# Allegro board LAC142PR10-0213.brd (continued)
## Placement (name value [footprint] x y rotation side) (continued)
R156  0_0603_5%  [R_0603]  33.04 74.76 90 top
R157  0_0603_5%  [R_0603]  43.57 64.96 270 top
R158  1K_0402_5%  [R_0402]  82.92 82.22 90 top
R159  1K_0402_5%  [R_0402]  94.47 86.68 0 bottom
R160  0_0603_5%  [R_0603]  162.36 18.35 270 bottom
R346  22K_0402_5%  [R_0402]  118.29 111.43 90 top
R347  22K_0402_5%  [R_0402]  144.51 95.38 0 top
R348  22K_0402_5%  [R_0402]  144.51 94.49 0 top
R365  100K_0402_5%  [R_0402]  63.3 169.88 270 top
R366  100K_0402_5%  [R_0402]  102.67 110.25 270 top
R384  10K_0402_5%  [R_0402]  63.3 173.43 270 top
R400  2K_0402_1%  [R_0402]  97.14 91.82 0 top
R401  150_0402_1%  [R_0402]  99.83 91.82 180 top
R404  1.69K_0402_1%  [R_0402]  116.72 90.42 180 top
R407  0_0402_5%  [R0402_0OHM]  63.3 171.65 270 top
R437  1K_0402_5%  [R_0402]  147.68 131.7 0 top
R438  47K_0402_5%  [R_0402]  147.68 134.37 0 top
R449  33_0402_5%  [R_0402]  148.18 88.32 0 top
R450  0_0402_5%  [R0402_0OHM]  142.06 84.2 180 bottom
R452  10K_0402_5%  [R_0402]  163.23 19.32 180 bottom
R541  196_0402_1%  [R_0402]  114.66 93.85 0 top
R542  196_0402_1%  [R_0402]  116.72 91.31 180 top
R602  33_0402_5%  [R_0402]  140.21 86.04 180 bottom
R616  100K_0402_1%  [R_0402]  86.42 159.83 0 bottom
R617  10_0402_5%  [R_0402]  158.82 82.36 180 bottom
R618  100K_0402_1%  [R_0402]  89.1 159.84 180 bottom
R634  10K_0402_5%  [R_0402]  138.17 93.03 0 bottom
R635  10K_0402_5%  [R_0402]  170.22 81.6 0 bottom
R636  10K_0402_5%  [R_0402]  138.17 90.37 0 bottom
R637  10K_0402_5%  [R_0402]  170.22 84.33 0 bottom
R638  10K_0402_5%  [R_0402]  141.14 83.25 0 bottom
R639  10K_0402_5%  [R_0402]  170.22 83.44 0 bottom
R640  10K_0402_5%  [R_0402]  170.22 82.49 0 bottom
R641  11.8K_0402_1%  [R_0402]  129.22 102.92 90 top
R642  10K_0402_5%  [R_0402]  157.91 83.68 0 bottom
R644  1K_0402_1%  [R_0402]  120.63 100.84 0 bottom
R645  1K_0402_1%  [R_0402]  119.39 99.95 180 bottom
R654  100K_0402_5%  [R_0402]  89.16 78.74 180 top
R661  0_0402_5%  [R_0402]  139.43 94.74 0 bottom
R662  0_0402_5%  [R_0402]  123.12 104.39 90 bottom
R663  0_0402_5%  [R_0402]  124.01 104.39 90 bottom
R664  0_0402_5%  [R0402_0OHM]  107.21 104.97 180 top
R669  33_0402_5%  [R_0402]  96.75 84.58 0 bottom
R670  33_0402_5%  [R_0402]  96.75 79.63 0 bottom
R671  33_0402_5%  [R_0402]  45.57 69.21 0 top
R672  33_0402_5%  [R_0402]  55.48 64.26 0 top
R673  0_0402_5%  [R0402_0OHM]  96.75 88.39 0 bottom
R675  33_0402_5%  [R_0402]  96.75 85.47 0 bottom
R676  2.2K_0402_5%  [R_0402]  139.28 82.87 180 bottom
R677  2.2K_0402_5%  [R_0402]  145.42 86.23 180 top
R679  0_0402_5%  [R_0402]  83.36 61.4 0 top
R680  0_0402_5%  [R_0402]  82.59 65.09 180 top
R681  33_0402_5%  [R_0402]  96.75 80.64 0 bottom
R682  0_0402_5%  [R_0402]  96.75 87.5 0 bottom
R683  0_0402_5%  [R_0402]  100.01 101.55 270 top
R685  4.7K_0402_5%  [R_0402]  164.78 33.48 270 bottom
R686  4.7K_0402_5%  [R_0402]  165.66 33.48 270 bottom
R688  10K_0402_5%  [R_0402]  136.65 93.98 270 top
R689  10K_0402_5%  [R_0402]  135.76 93.98 270 top
R690  10K_0402_5%  [R_0402]  141.75 37.87 90 top
R691  10K_0402_5%  [R_0402]  142.93 88.63 90 bottom
R692  10K_0402_5%  [R_0402]  145.42 91.57 180 top
R693  10K_0402_5%  [R_0402]  144.51 90.68 0 top
R694  10K_0402_5%  [R_0402]  121.71 117.28 0 top
R695  10K_0402_5%  [R_0402]  135.17 100.58 0 top
R696  10K_0402_5%  [R_0402]  129.79 101.68 270 bottom
R703  0_0402_5%  [R_0402]  102.8 101.55 270 top
R704  0_0402_5%  [R_0402]  96.65 89.66 180 top
R705  0_0402_5%  [R_0402]  96.65 90.55 180 top
R709  10K_0402_5%  [R_0402]  138.17 88.59 0 bottom
R808  300_0402_5%  [R_0402]  10.72 18.17 270 bottom
R809  300_0402_5%  [R_0402]  23.3 19.99 90 bottom
R810  300_0402_5%  [R_0402]  27.49 29.16 270 top
R811  300_0402_5%  [R_0402]  23.55 42.34 90 top
R902  10K_0402_5%  [R_0402]  146.41 90.68 0 top
R903  2K_0402_5%  [R_0402]  147.33 91.57 180 top
R904  10K_0402_5%  [R_0402]  146.41 88.01 0 top
R905  100K_0402_5%  [R_0402]  125.66 106.5 270 top
R907  33_0402_5%  [R_0402]  125.53 101.55 270 bottom
R914  20M_0402_5%  [R_0402]  133.1 103.38 180 bottom
R916  100K_0402_5%  [R_0402]  55.05 47.07 270 bottom
R917  100K_0402_5%  [R_0402]  55 51.31 180 bottom
R918  100K_0402_5%  [R_0402]  54.16 47.07 270 bottom
R925  10K_0402_5%  [R_0402]  143.82 85.04 270 bottom
R926  2K_0402_5%  [R_0402]  148.18 87.44 0 top
R927  2K_0402_5%  [R_0402]  142.93 84.12 90 bottom
R928  10K_0402_5%  [R_0402]  128.33 106.5 270 top
R929  2K_0402_5%  [R_0402]  129.22 105.59 90 top
R930  10K_0402_5%  [R_0402]  124.9 105.31 270 bottom
R931  10K_0402_5%  [R_0402]  140.52 100.15 270 bottom
R932  10K_0402_5%  [R_0402]  139.63 100.15 270 bottom
R934  10K_0402_5%  [R_0402]  145.42 88.01 180 top
R935  10K_0402_5%  [R_0402]  145.42 88.9 180 top
R936  10K_0402_5%  [R_0402]  145.42 89.79 180 top
R937  10K_0402_5%  [R_0402]  139.64 79.28 180 bottom
R938  10K_0402_5%  [R_0402]  146.79 133.45 90 top
R939  1M_0402_5%  [R_0402]  109.02 105.04 0 bottom
R940  1M_0402_5%  [R_0402]  165.18 22.14 90 bottom
R941  10K_0402_5%  [R_0402]  139.64 80.17 180 bottom
R942  10K_0402_5%  [R_0402]  121.55 99.95 180 bottom
R943  100K_0402_5%  [R_0402]  141.41 100.15 270 bottom
R944  100K_0402_5%  [R_0402]  124.78 117.28 180 top
R949  10K_0402_5%  [R_0402]  114.86 100.79 270 bottom
R950  2.2K_0402_5%  [R_0402]  115.75 99.87 90 bottom
R951  10K_0402_5%  [R_0402]  124.26 100.91 270 bottom
R952  2.2K_0402_5%  [R_0402]  123.37 100 90 bottom
R953  2.2K_0402_5%  [R_0402]  126.55 105.59 90 top
R954  10K_0402_5%  [R_0402]  127.44 106.5 270 top
R955  2.2K_0402_5%  [R_0402]  141.5 88.4 180 bottom
R956  2.2K_0402_5%  [R_0402]  140.87 89.29 180 bottom
R1160  4.7K_0402_5%  [R_0402]  100.89 100.63 90 top
R1161  4.7K_0402_5%  [R_0402]  103.69 100.63 90 top
R1563  100K_0402_5%  [R_0402]  190.81 81.58 90 top
R1671  470_0603_5%  [R_0603]  148.14 103.57 90 top
R1672  0_0603_5%  [R_0603]  157.41 84.77 0 bottom
R1673  0_0603_5%  [R_0603]  157.41 86.04 0 bottom
R1674  4.7K_0402_5%  [R_0402]  144.33 101.14 90 bottom
R1675  0_0603_5%  [R_0603]  165.58 71.95 90 top
R1690  0_0402_5%  [R0402_0OHM]  176.54 84.71 180 bottom
R1691  0_0402_5%  [R_0402]  140.93 92.4 180 bottom
R1692  0_0402_5%  [R_0402]  139.09 89.48 180 bottom
R1693  0_0402_5%  [R_0402]  141.58 91.1 180 bottom
R1694  0_0402_5%  [R_0402]  139.09 91.27 180 bottom
R2313  0_0402_5%  [R0402_0OHM]  36 24.33 270 top
R2318  0_0402_5%  [R0402_0OHM]  32.44 24.33 270 top
R2448  10K_0402_5%  [R_0402]  150.81 32.31 90 top
R2450  0_0402_5%  [R_0402]  149.92 33.22 270 top
R2634  100K_0402_5%  [R_0402]  55.94 47.07 270 bottom
R2635  100K_0402_5%  [R_0402]  56.83 47.07 270 bottom
R2636  100K_0402_5%  [R_0402]  57.97 46.15 90 bottom
R5409  0R3J-0-U-GP  [R_0603]  19.17 78.01 90 top
R6103  470R2J-2-GP  [R_0402]  24.99 3.01 0 top
R6104  0R2J-2-GP  [R_0402]  65.46 14.02 90 bottom
R6105  0R2J-2-GP  [R_0402]  65.46 9.96 90 bottom
R6106  0R2J-2-GP  [R_0402]  28 9.47 270 top
R6107  390R2J-3-GP  [R_0402]  25 3.92 0 top
R6108  330R2J-3-GP  [R_0402]  23.72 2.95 180 top
R6110  10KR2J-3-GP  [R_0402]  29.98 6.22 180 bottom
RA5  470K_0402_5%  [R_0402]  179.31 21.49 0 bottom
RA6  10K_0402_5%  [R_0402]  178.22 15.11 180 bottom
RA8  0_0402_5%  [R0402_0OHM]  186.8 6.74 90 bottom
RA10  0_0402_5%  [R0402_0OHM]  184.84 22.68 270 bottom
RA12  100K_0402_5%  [R_0402]  189.44 16.15 180 bottom
RA13  100K_0402_5%  [R_0402]  180.22 19.18 180 bottom
RA19  10K_0402_5%  [R_0402]  178.35 18.26 180 bottom
RA29  0_0603_1%  [R0603_0OHM]  186.62 21.65 90 bottom
RA30  0_0603_1%  [R0603_0OHM]  193.8 21.34 0 bottom
RA31  0_0603_1%  [R0603_0OHM]  190.98 7.74 270 bottom
RA32  0_0603_1%  [R0603_0OHM]  192.91 8 0 bottom
RA34  200K_0402_1%  [R_0402]  180.22 18.29 180 bottom
RA53  2.2K_0402_5%  [R_0402]  182.85 18.88 180 bottom
RA55  10_0402_5%  [R_0402]  190.81 10.63 0 bottom
RA56  10_0402_5%  [R_0402]  188.91 11.81 0 bottom
RA79  1K_0402_1%  [R_0402]  177.44 17.37 0 bottom
RA80  1K_0402_1%  [R_0402]  192.61 10.64 270 bottom
RA81  10K_0402_5%  [R_0402]  175.6 17.37 0 bottom
RA82  1K_0402_1%  [R_0402]  191.73 11.51 90 bottom
RA83  10K_0402_5%  [R_0402]  191.73 8.84 180 bottom
RA84  10K_0402_5%  [R_0402]  190.84 12.42 270 bottom
RA130  22_0402_5%  [R_0402]  177.32 14.11 0 bottom
RA165  4.7K_0402_5%  [R_0402]  190.81 9.73 0 bottom
RA166  4.7K_0402_5%  [R_0402]  189.03 12.73 0 bottom
RA1109  2.2K_0402_5%  [R_0402]  181.1 17.97 90 bottom
RA1110  0_0603_1%  [R0603_0OHM]  178.92 6.49 90 bottom
RA1111  0_0603_1%  [R0603_0OHM]  189.91 19.44 180 bottom
RA1112  0_0402_5%  [R_0402]  178.24 11.89 180 bottom
RA1113  0_0402_5%  [R_0402]  177.32 10.74 0 bottom
RC7  2.2K_0402_5%  [R_0402]  106.36 110.16 90 top
RC8  2.2K_0402_5%  [R_0402]  103.69 112.09 270 top
RC9  0_0402_5%  [R_0402]  106.36 108.38 90 top
RC10  0_0402_5%  [R_0402]  102.67 111.18 90 top
RD15  0_0402_5%  [R_0402]  196.35 76.33 180 top
RD16  0_0402_5%  [R_0402]  166.19 39.52 0 top
RD19  0_0402_5%  [R0402_0OHM]  196.35 75.44 180 top
RE4  0_0805_5%  [R_0805]  173.45 65.66 0 top
RE13  0_0805_5%  [R_0805]  173.45 67.44 0 top
RE14  0_0402_5%  [R0402_0OHM]  185.98 61.29 270 top
RE15  0_0402_5%  [R0402_0OHM]  189.79 77.29 270 bottom
RE16  33_0402_5%  [R_0402]  195.43 69.85 0 top
RE17  47K_0402_5%  [R_0402]  189.03 81.58 90 top
RE19  1K_0402_1%  [R_0402]  192.77 72.01 0 bottom
RE20  100K_0402_1%  [R_0402]  174.76 79.37 180 top
RE21  10K_0402_5%  [R_0402]  196.35 78.23 180 top
RE22  0_0402_1%  [R_0402]  173.84 78.49 0 top
RE23  100K_0402_1%  [R_0402]  177.98 61.29 270 top
RE24  0_0402_1%  [R_0402]  177.09 60.38 90 top
RE25  0_0402_5%  [R_0402]  170.48 68.83 0 bottom
RE26  0_0402_5%  [R_0402]  170.48 69.72 0 bottom
RE27  4.7K_0402_5%  [R_0402]  173.84 68.83 0 top
RE28  4.7K_0402_5%  [R_0402]  173.84 69.72 0 top
RE30  47K_0402_5%  [R_0402]  178.99 65.6 0 bottom
RE31  0_0402_5%  [R0402_0OHM]  173.84 75.06 0 top
RE32  10K_0402_5%  [R_0402]  196.35 73.58 180 top
RE33  0_0402_5%  [R0402_0OHM]  173.84 74.17 0 top
RE35  0_0402_5%  [R0402_0OHM]  173.84 72.39 0 top
RE39  0_0402_5%  [R0402_0OHM]  183.32 60.38 90 top
RE42  0_0402_5%  [R0402_0OHM]  173.84 73.28 0 top
RE46  4.7K_0402_5%  [R_0402]  192.84 61.29 270 top
RE48  4.7K_0402_5%  [R_0402]  179.76 61.29 270 top
RE49  100K_0402_5%  [R_0402]  160.25 64.13 0 top
RE53  0_0402_5%  [R0402_0OHM]  196.35 67.44 180 top
RE54  0_0402_5%  [R0402_0OHM]  196.35 70.74 180 top
RE55  0_0402_5%  [R0402_0OHM]  193.68 71.12 180 bottom
RE56  0_0402_5%  [R0402_0OHM]  196.35 77.34 180 top
RE58  100K_0402_5%  [R_0402]  189.74 121.41 180 top
RE59  0_0805_5%  [R_0805]  196.49 133.35 180 top
RE60  240_0402_1%  [R_0402]  191.64 88.63 90 top
RE61  10K_0402_5%  [R_0402]  196.35 72.69 180 top
RE62  47K_0402_5%  [R_0402]  188.91 76.38 90 bottom
RE63  47K_0402_5%  [R_0402]  188.02 76.38 90 bottom
RE64  0_0402_5%  [R0402_0OHM]  198.25 64.45 180 top
RE65  0_0402_5%  [R0402_0OHM]  173.84 85.6 0 bottom
RE66  0_0402_1%  [R0402_0OHM]  173.84 84.71 0 bottom
RE67  100K_0402_5%  [R_0402]  183.44 67.39 270 bottom
RE68  10K_0402_5%  [R_0402]  187.05 121.41 0 top
RE69  0_0402_5%  [R_0402]  198.25 63.56 180 top
RE70  10K_0402_5%  [R_0402]  179 66.47 90 bottom
RE71  0_0402_5%  [R0402_0OHM]  181.54 61.29 270 top
RE72  10K_0402_5%  [R_0402]  97.16 135.51 180 bottom
RE73  240_0402_1%  [R_0402]  195.78 112.94 90 top
RE75  10K_0402_5%  [R_0402]  165.25 42.05 90 top
RE80  0_0402_5%  [R0402_0OHM]  174.76 76.71 180 top
RE330  0_0603_1%  [R0603_0OHM]  54.6 80.26 0 top
RE331  0_0603_5%  [R_0603]  54.6 78.99 0 top
RE336  0_0402_5%  [R_0402]  59.16 74.42 0 top
RE337  0_0402_5%  [R_0402]  59.16 75.31 0 top
RE338  0_0402_5%  [R0402_0OHM]  59.16 76.2 0 top
RE340  10K_0402_5%  [R_0402]  58.21 77.08 90 top
RE341  10K_0402_5%  [R_0402]  59.16 77.09 0 top
RE504  10K_0402_5%  [R_0402]  181.08 68.26 0 bottom
RH1  100K_0402_5%  [R_0402]  141.15 85.14 90 bottom
RH25  33_0402_5%  [R_0402]  130.23 103.81 90 top
RH26  8.2K_0402_5%  [R_0402]  130.23 106.5 270 top
RH27  0_0402_5%  [R_0402]  132.19 103.5 0 top
RH28  0_0402_5%  [R_0402]  131.12 104.72 270 top
RH29  0_0402_5%  [R_0402]  55.63 165.35 180 top
RH30  0_0402_5%  [R0402_0OHM]  131.2 102.87 180 top
RH31  0_0402_5%  [R0402_0OHM]  52.94 165.35 0 top
RH32  0_0402_5%  [R0402_0OHM]  171.33 49.28 180 top
RH40  10K_0402_5%  [R_0402]  145.42 87.12 180 top
RH41  10K_0402_5%  [R_0402]  146.41 89.79 0 top
RH42  10K_0402_5%  [R_0402]  146.41 88.9 0 top
RH43  10K_0402_5%  [R_0402]  196.35 74.55 180 top
RH44  10K_0402_5%  [R_0402]  149.66 54.15 90 top
RH45  10K_0402_5%  [R_0402]  150.62 54.15 90 top
RH46  10K_0402_5%  [R_0402]  148.71 54.15 90 top
RH51  0_0402_5%  [R_0402]  144.51 92.71 0 top
RH52  0_0402_5%  [R0402_0OHM]  144.51 93.6 0 top
RH53  0_0402_5%  [R0402_0OHM]  145.47 97.23 270 top
RH54  0_0402_5%  [R_0402]  165.23 64.39 180 top
RH55  100K_0402_5%  [R_0402]  126.29 109.42 270 top
RH56  0_0402_5%  [R_0402]  138.37 81.98 0 bottom
RH57  0_0402_5%  [R_0402]  165.23 68.07 180 top
RI1  0_0402_5%  [R_0402]  189.87 35.81 180 top
RI2  0_0402_5%  [R_0402]  189.73 30.24 270 top
RL1  0_0603_5%  [MURAT_BLM18AG601SN1D_L0603_2P]  53.52 170.6 90 top
RL6  0_0603_1%  [R0603_0OHM]  53.9 166.43 180 bottom
RL19  75_0603_5%  [R_0603]  15.53 168.94 90 bottom
RL20  75_0603_5%  [R_0603]  15.52 172.73 270 bottom
RL27  100K_0402_5%  [R_0402]  36.38 178 270 top
RL31  2.49K_0402_1%~D  [R_0402]  44.89 173.43 270 top
RL33  1K_0402_5%  [R_0402]  55.63 166.5 180 top
RL34  10K_0402_5%  [R_0402]  50.73 166.93 90 bottom
RL35  15K_0402_1%  [R_0402]  53.85 166.5 180 top
RL37  10K_0402_5%  [R_0402]  48.19 164.29 270 top
RL38  10K_0402_5%  [R_0402]  37.27 177.09 90 top
RL39  10K_0402_5%  [R_0402]  50.73 174.96 270 top
RL40  10K_0402_5%  [R_0402]  34.35 173.91 90 top
RL41  75_0603_5%  [R_0603]  15.52 168.94 90 top
RL42  75_0603_5%  [R_0603]  15.52 172.73 270 top
RM6  0_0402_5%  [R_0402]  170.41 50.16 0 top
RM7  0_1206_5%  [R_1206]  177.54 41.59 180 bottom
RM8  10K_0402_5%~D  [R_0402]  170.41 48.39 0 top
RM9  100K_0402_5%  [R_0402]  171.46 52.7 180 top
RM10  0_1206_5%  [R_1206]  177.54 39.56 180 bottom
RP13  33_0804_8P4R_5%  [RP_0804_8P4R]  140.78 97.46 180 bottom
RP20  2.2K_0804_8P4R_5%  [RP_0804_8P4R]  161.67 29.98 180 top
RP24  2.2K_0804_8P4R_5%  [RP_0804_8P4R]  161.67 26.94 180 top
RP25  1K_0804_8P4R_5%  [RP_0804_8P4R]  96.39 83.3 180 bottom
RP27  1K_0804_8P4R_5%  [RP_0804_8P4R]  55.87 62.85 0 top
RP28  1K_0804_8P4R_5%  [RP_0804_8P4R]  55.87 72 0 top
RP30  1K_0804_8P4R_5%  [RP_0804_8P4R]  94.22 88.51 0 top
RP34  10K_8P4R_5%  [RP_0804_8P4R]  186.35 140.33 270 bottom
RP45  100K_0804_8P4R_5%  [RP_0804_8P4R]  101.39 104.59 270 top
RP58  499_0804_8P4R_1%  [RP_0804_8P4R]  24.29 63.43 0 top
RP59  499_0804_8P4R_1%  [RP_0804_8P4R]  24.41 70.16 0 top
RP62  75_0804_8P4R_1%  [RP_0804_8P4R]  31.36 69.71 0 top
RP63  2.2K_0804_8P4R_5%  [RP_0804_8P4R]  30.36 72.87 0 bottom
RPE1  2.2K_0804_8P4R_5%  [RP_0804_8P4R]  181.35 74.22 180 bottom
RR1  6.19K_0402_1%  [R_0402]  13.79 17.14 180 bottom
RR2  22_0402_5%  [R_0402]  21.17 19.75 0 bottom
RR3  22_0402_5%  [R_0402]  16.62 23.28 90 bottom
RS6  470K_0402_5%  [R_0402]  153.6 96.7 90 top
RS8  0_0402_5%  [R_0402]  192.02 40.89 270 bottom
RS18  0_0402_5%  [R_0402]  184.78 26.05 270 bottom
RS19  0_0402_5%  [R0402_0OHM]  181.6 36.46 270 bottom
RS20  0_0402_5%  [R_0402]  183.89 27.29 90 bottom
RS21  0_0402_5%  [R_0402]  182.49 35.55 90 bottom
RS22  0_0402_5%  [R0402_0OHM]  183.83 25.13 90 bottom
RS23  0_0402_5%  [R_0402]  182.75 26.05 270 bottom
RS24  2K_0402_5%  [R_0402]  185.16 35.55 90 bottom
RS25  0_0402_5%  [R0402_0OHM]  186.05 36.46 270 bottom
RS26  0_0402_5%  [R0402_0OHM]  181.86 27.29 90 bottom
RS27  0_0402_5%  [R_0402]  184.27 36.46 270 bottom
RS28  0_0402_5%  [R_0402]  183.38 36.46 270 bottom
RS29  0_0402_5%  [R_0402]  184.78 27.29 90 bottom
RS30  0_0402_5%  [R_0402]  182.75 27.29 90 bottom
RS31  5.1K_0402_1%  [R_0402]  180.97 28.21 270 bottom
RS33  4.7K_0402_5%  [R_0402]  180.71 35.55 90 bottom
RS34  4.7K_0402_5%  [R_0402]  185.92 28.21 270 bottom
RS35  4.7K_0402_5%  [R_0402]  179.83 35.55 90 bottom
RS36  4.7K_0402_5%  [R_0402]  185.92 26.05 270 bottom
RS37  0_0402_5%  [R0402_0OHM]  186.99 32.32 0 bottom
RS38  0_0402_5%  [R_0402]  186.99 31.43 0 bottom
RS41  0_0402_5%  [R_0402]  178.73 30.54 0 top
RS42  0_0402_5%  [R_0402]  178.73 31.43 0 top
RS43  0_0402_5%  [R_0402]  178.73 33.21 0 top
RS44  0_0402_5%  [R_0402]  178.73 32.32 0 top
RS45  0_0402_5%  [R_0402]  197.5 23.6 90 bottom
RV1  1K_0402_1%  [R_0402]  153.41 130.21 180 bottom
RV2  1K_0402_1%  [R_0402]  171.51 136.24 0 top
RV3  1K_0402_1%  [R_0402]  153.4 129.3 180 bottom
RV4  100K_0402_5%  [R_0402]  158.57 119.09 0 bottom
RV5  45.3K_0402_1%  [R_0402]  175.48 129.82 90 top
RV6  45.3K_0402_1%  [R_0402]  175.48 132.53 270 top
RV8  8.45K_0402_1%  [R_0402]  167.22 120.97 90 top
RV9  2K_0402_1%  [R_0402]  167.22 122.77 0 top
RV11  8.45K_0402_1%  [R_0402]  168.99 120.99 90 top
RV12  4.75K_0402_1%  [R_0402]  168.98 122.78 0 top
RV13  4.75K_0402_1%  [R_0402]  170.75 122.76 0 top
RV15  8.45K_0402_1%  [R_0402]  165.45 120.98 90 top
RV16  4.75K_0402_1%  [R_0402]  165.45 122.77 0 top
RV17  1K_0402_1%  [R_0402]  184.59 138.01 180 top
RV20  1M_0402_5%  [R_0402]  162.34 119.13 0 bottom
RV21  10K_0402_5%  [R_0402]  177.54 135.04 180 top
RV27  0_0603_5%  [R0603_0OHM]  175.62 122.98 90 top
RV28  8.45K_0402_1%  [R_0402]  170.76 120.99 90 top
RV29  10K_0402_5%  [R_0402]  160.02 127.6 270 top
RV30  0_0603_5%  [R0603_0OHM]  167.91 125.38 90 top
RV31  0_0805_5%  [R0805_0OHM]  162.07 131.9 270 top
RV32  40.2_0402_1%  [R_0402]  161.08 137.94 180 top
RV33  40.2_0402_1%  [R_0402]  155.94 137.16 0 top
RV34  100_0402_1%  [R_0402]  157.73 137.55 270 top
RV35  100_0402_1%  [R_0402]  158.63 139.38 180 top
RV36  49.9_0402_1%  [R_0402]  184.82 140.67 270 bottom
RV37  10_0402_1%  [R_0402]  183.92 138.88 0 bottom
RV38  5.1K_0402_1%  [R_0402]  183.04 138.89 90 bottom
RV39  120_0402_1%  [R_0402]  153.41 138.32 270 bottom
RV40  51.1_0402_1%  [R_0402]  181.49 136.26 180 top
RV41  51.1_0402_1%  [R_0402]  181.5 137.17 180 top
RV42  4.99K_0402_1%  [R_0402]  165 167.31 180 bottom
RV43  4.99K_0402_1%  [R_0402]  152.53 165.78 0 top
RV44  4.99K_0402_1%  [R_0402]  164.09 166.42 0 bottom
RV45  4.99K_0402_1%  [R_0402]  153.45 164.89 180 top
RV46  243_0402_1%  [R_0402]  164.16 163.67 90 bottom
RV47  243_0402_1%  [R_0402]  153.45 163.12 180 top
RV48  40.2_0402_1%  [R_0402]  153.45 162.23 180 bottom
RV49  40.2_0402_1%  [R_0402]  153.45 163.12 180 bottom
RV50  4.99K_0402_1%  [R_0402]  189.62 159.81 180 top
RV51  4.99K_0402_1%  [R_0402]  189.62 166.29 180 bottom
RV52  4.99K_0402_1%  [R_0402]  188.7 160.7 0 top
RV53  4.99K_0402_1%  [R_0402]  188.7 165.4 0 bottom
RV54  40.2_0402_1%  [R_0402]  188.7 162.61 0 bottom
RV55  40.2_0402_1%  [R_0402]  188.7 161.72 0 bottom
RV56  243_0402_1%  [R_0402]  177.98 163.55 90 top
RV57  243_0402_1%  [R_0402]  188.7 163.5 0 bottom
RV58  4.7K_0402_5%  [R_0402]  181.76 132.92 270 top
RV59  10K_0402_5%  [R_0402]  159.14 127.61 270 top
RV60  0_0603_1%  [R0603_0OHM]  176.01 128.3 0 top
RV71  10K_0402_5%  [R_0402]  181.6 135.49 270 bottom
RV72  10K_0402_5%  [R_0402]  187.18 132.71 0 bottom
RV73  10K_0402_5%  [R_0402]  182.49 134.57 90 bottom
RV74  10K_0402_5%  [R_0402]  188.09 133.64 180 bottom
RV75  0_0402_5%  [R_0402]  179.76 135.49 0 bottom
RV76  0_0402_5%  [R_0402]  188.08 131.79 180 bottom
RV77  33_0402_5%  [R_0402]  189.59 134.87 0 bottom
RV78  33_0402_5%  [R_0402]  189.59 135.76 0 bottom
RV79  10K_0402_5%  [R_0402]  189.29 138.99 90 bottom
RV81  4.7K_0402_5%  [R_0402]  179.83 130.04 0 bottom
RV82  4.7K_0402_5%  [R_0402]  182.98 130.02 180 bottom
RV83  16.2K_0402_1%  [R_0402]  181.96 128.11 0 bottom
RV84  10K_0402_5%  [R_0402]  190.51 135.76 180 top
RV87  10K_0402_5%  [R_0402]  190.51 134.87 180 top
RV88  10K_0402_5%  [R_0402]  189.59 133.98 0 top
RV89  10K_0402_5%  [R_0402]  189.59 136.65 0 top
RV90  0_0402_5%  [R_0402]  179.47 134.39 270 top
RV91  10K_0402_5%  [R_0402]  180.39 134.38 270 top
RV92  0_0402_5%  [R_0402]  183.18 128.42 0 top
RV93  0_0603_1%  [R0603_0OHM]  181.24 127.08 90 top
RV94  0_0603_5%  [R_0603]  179.98 127.07 90 top
RV146  4.7K_0402_5%  [R_0402]  183.59 132.02 0 top
RV147  4.7K_0402_5%  [R_0402]  186.58 130.13 180 top
RV148  100K_0402_5%  [R_0402]  183.17 127.51 0 top
RV149  0_0402_5%  [R_0402]  181.76 130.18 90 top
RV151  10K_0402_5%  [R_0402]  181.7 136.58 180 bottom
RV152  10K_0402_5%  [R_0402]  184.9 140.85 0 top
RV153  0_0402_5%  [R_0402]  177.67 134.14 180 top
RV154  5.1K_0402_1%  [R_0402]  184.59 137.08 180 top
RV155  0_0402_5%  [R_0402]  170.33 120.02 270 bottom
RV156  0_0402_5%  [R_0402]  171.24 120.02 270 bottom
RV157  0_0402_5%  [R_0402]  172.19 120.02 270 bottom
RV158  0_0402_5%  [R_0402]  163.69 123.69 270 top
RV159  0_0402_5%  [R_0402]  162.79 123.69 270 top
RV160  10_0402_5%  [R_0402]  164.59 122.77 90 top
RV161  10_0402_5%  [R_0402]  161.89 122.79 90 top
RV162  4.7K_0402_5%  [R_0402]  160.95 122.31 90 top
RV163  4.7K_0402_5%  [R_0402]  160.03 123.2 90 top
RV164  0_0402_5%  [R_0402]  184.75 130.05 270 bottom
RV165  0_0402_5%  [R_0402]  183.84 130.04 270 bottom
RV166  0_0402_5%  [R_0402]  184.93 125.68 90 top
RV167  0_0402_5%  [R_0402]  184.04 125.69 90 top
RV168  0_0402_5%  [R_0402]  189.57 131.71 0 top
RV169  0_0402_5%  [R_0402]  189.57 132.64 0 top
RV254  0_0402_5%  [R_0402]  176.84 126.75 270 top
RV255  0_0402_5%  [R_0402]  177.73 126.75 270 top
RX2  100_0402_5%  [R_0402]  85.54 158.95 90 bottom
RX3  100_0402_5%  [R_0402]  87.26 156.62 90 top
RX4  0_0805_5%  [R_0805]  76.9 160.99 0 bottom
RX7  0_0402_5%  [R0402_0OHM]  82.26 152.88 0 bottom
RX8  0_0402_5%  [R_0402]  82.26 151.99 0 bottom
RX9  10K_0402_5%  [R_0402]  94.42 159.8 270 bottom
RX10  10K_0402_5%  [R_0402]  84.7 153.73 90 bottom
RX11  0_0402_5%  [R_0402]  85.48 156.62 90 top
RX12  10K_0402_5%  [R_0402]  26.02 75.37 180 top
RX13  100K_0402_5%  [R_0402]  27.58 63.63 0 top
RX14  100K_0402_5%  [R_0402]  26.02 74.48 180 top
RX15  150K_0402_5%  [R_0402]  26.02 76.26 180 top
RX16  10K_0402_5%  [R_0402]  86.37 156.62 90 top
RX17  0_0402_5%  [R_0402]  104.97 164.85 180 bottom
RX18  0_0402_5%  [R_0402]  104.97 160.34 180 bottom
RX19  0_0402_5%  [R_0402]  104.97 163.96 180 bottom
RX20  0_0402_5%  [R_0402]  91.61 152.21 0 top
RX21  0_0402_5%  [R_0402-NPM]  95.18 161.09 90 bottom
RX22  0_0402_5%  [R_0402-NPM]  96.45 161.09 90 bottom
RX23  0_0402_1%  [R0402_0OHM]  85.41 156.71 90 bottom
RX24  100K_0402_5%  [R_0402]  104.97 163.07 180 bottom
RX25  33_0402_5%  [R_0402]  104.06 162.12 0 bottom
RX26  100K_0402_5%  [R_0402]  93.53 159.8 270 bottom
RX27  0_0603_1%  [R0603_0OHM]  97.5 160.81 90 bottom
RX28  0_0603_1%  [R0603_0OHM]  86.43 150.83 180 top
RX29  0_0603_1%  [R0603_0OHM]  82.54 151.35 0 top
RX30  0_0603_5%  [R_0603]  82.54 152.59 0 top
RX31  0_0402_5%  [R_0402-NPM]  21.02 68.83 180 bottom
RX32  0_0402_5%  [R_0402-NPM]  21.02 67.56 180 bottom
RX34  20K_0402_5%  [R_0402]  25.1 77.15 0 top
RX35  100K_0402_5%  [R_0402]  104.97 161.23 180 bottom
RX36  0_0402_5%  [R_0402]  84.58 159.87 270 bottom
RX37  0_0402_5%  [R_0402-NPM]  21.02 72.45 180 bottom
RX38  0_0402_5%  [R_0402-NPM]  21.02 71.18 180 bottom
RX39  0_0402_5%  [R_0402-NPM]  21.02 65.02 180 bottom
RX40  0_0402_5%  [R_0402-NPM]  21.02 63.88 180 bottom
RX41  0_0402_5%  [R_0402-NPM]  21.02 60.2 180 bottom
RX42  0_0402_5%  [R_0402-NPM]  21.02 61.34 180 bottom
RX43  150_0402_5%  [R_0402]  17.71 68.66 270 bottom
RX44  150_0402_5%  [R_0402]  17.71 72.34 270 bottom
RX45  150_0402_5%  [R_0402]  17.71 64.97 270 bottom
RX46  150_0402_5%  [R_0402]  17.71 60.38 90 bottom
RZ1  4.7K_0402_5%  [R_0402]  39.17 62.28 90 top
RZ2  4.7K_0402_5%  [R_0402]  39.17 64.06 90 top
RZ3  4.7K_0402_5%  [R_0402]  40.19 62.28 90 top
RZ4  4.7K_0402_5%  [R_0402]  40.19 64.06 90 top
RZ5  4.7K_0402_5%  [R_0402]  38.16 62.28 90 top
RZ6  4.7K_0402_5%  [R_0402]  38.16 64.06 90 top
RZ10  100K_0402_5%  [R_0402]  53.9 31.29 90 bottom
RZ19  100K_0402_5%  [R_0402]  52.13 27.13 270 bottom
RZ21  100K_0402_5%  [R_0402]  53.02 31.29 90 bottom
RZ42  100K_0402_5%  [R_0402]  40.89 74.03 90 top
RZ45  12K_0402_1%  [R_0402]  42.14 68.2 0 top
RZ47  36_0402_5%  [R_0402]  34.73 73.98 90 top
RZ49  36_0402_5%  [R_0402]  36 73.98 90 top
RZ51  0_0402_5%  [R_0402]  26.67 55.84 90 top
RZ52  0_0402_5%  [R_0402]  26.63 57.94 90 top
RZ53  0_0402_5%  [R_0402]  26.64 60.68 270 top
RZ54  2.2K_0402_5%  [R_0402]  14.06 79.46 180 top
RZ55  2.2K_0402_5%  [R_0402]  14.06 78.57 180 top
RZ591  10K_0402_5%  [R_0402]  53.02 27.13 270 bottom
RZ1045  0_0402_5%  [R_0402]  44.63 74.03 90 top
RZ1046  0_0402_5%  [R_0402]  43.74 74.03 90 top
RZ1047  0_0402_5%  [R_0402]  42.86 74.03 90 top
RZ1048  0_0402_5%  [R_0402]  41.97 74.03 90 top
RZ1049  0_0402_5%  [R_0402]  97.21 75.87 90 bottom
SW1  SMT1-05-A_4P  [SW_SMT1-05-A_4P]  158.35 69.76 0 top
T12  -  [TPC12]  100.77 66.61 180 bottom
T13  -  [TPC12]  127.68 73.53 0 top
T26  -  [TPC12]  173.71 22.08 0 bottom
T27  -  [TPC12]  16.85 59.4 0 top
T28  -  [TPC12]  95.31 85.72 0 top
T29  -  [TPC12]  106.15 82.28 0 top
T30  -  [TPC12]  106.86 84.96 0 top
T31  -  [TPC12]  106.1 83.69 0 top
T32  -  [TPC12]  124.16 77.87 0 top
T33  -  [TPC12]  125.37 77.84 0 top
T34  -  [TPC12]  113.21 77.34 0 top
T35  -  [TPC12]  111.44 77.23 0 top
T36  -  [TPC12]  127.97 78.45 0 top
T38  -  [TPC12]  119.37 90.61 0 top
T39  -  [TPC12]  117.55 89.19 0 top
T40  -  [TPC12]  98.48 89.92 0 top
T41  -  [TPC12]  113.32 75.23 0 top
T42  -  [TPC12]  93.9 85.88 0 top
T43  -  [TPC12]  90.98 86.04 0 top
T44  -  [TPC12]  108.38 87.68 0 top
T45  -  [TPC12]  97.21 78.1 180 bottom
T46  -  [TPC12]  109.91 154.28 0 top
T86  PAD  [TPC12]  179.23 138.95 0 top
T94  PAD  [TPC12]  51.03 172.62 270 top
T95  PAD  [TPC12]  49.08 171.7 270 top
T173  -  [TPC12]  102.23 66.61 180 bottom
T201  -  [TPC12]  173.58 137.34 0 top
T202  -  [TPC12]  172.76 138.38 0 top
T203  -  [TPC12]  172.42 126.36 0 top
T204  -  [TPC12]  170.98 130.39 0 top
T205  -  [TPC12]  174.09 126.38 0 top
T206  -  [TPC12]  173.29 126.35 0 top
T207  -  [TPC12]  172.37 127.07 0 top
T208  -  [TPC12]  174.09 127.16 0 top
T209  -  [TPC12]  173.28 127.17 0 top
T210  -  [TPC12]  175 127.7 0 top
T211  -  [TPC12]  172.1 128.42 0 top
T212  -  [TPC12]  174.67 128.94 0 top
T213  -  [TPC12]  174.59 130.37 0 top
T214  -  [TPC12]  182.35 126.97 180 bottom
T215  -  [TPC12]  181.06 127.11 180 bottom
T216  -  [TPC12]  182.92 129.12 180 bottom
T217  -  [TPC12]  181.08 129.01 180 bottom
T218  -  [TPC12]  166.36 129.5 0 top
T221  -  [TPC12]  179.91 127.77 180 bottom
T222  -  [TPC12]  179.72 129.12 180 bottom
T223  -  [TPC12]  179.42 133.9 180 bottom
T224  -  [TPC12]  180.54 134.59 180 bottom
T4933  PAD~D  [TPC12]  33.58 66.42 180 top
T4934  PAD~D  [TPC12]  34.09 64.64 180 top
T4935  -  [TPC12]  173.07 120.2 180 bottom
TL1  350UH_LF-H1201P-2  [LANKO_LF-H1201P-2_16P]  26.56 175.28 270 bottom
TL2  350UH_LF-H1201P-2  [LANKO_LF-H1201P-2_16P]  26.56 166.39 90 top
U1  S IC SN74AVC2T45DCTR_SM8  [SN74LVC2T45DCTR_SM8]  184.06 134.88 90 bottom
U2  -  [LM393DR_SO8]  37.99 55.5 90 bottom
U4  AO4354_SO8  [AO4430L_SO8]  149.03 103.97 180 bottom
U5  -  [MC74VHC1G08DFT2G_SC70-5]  167.53 37.13 90 top
U15  EM5209VF DFN 14P DUAL LOAD SW  [TPS22966DPUR_SON14_2X3]  150.16 133.79 270 top
U56  W25Q64FWSSIQ_SO8  [W25Q64DWSSIG_SO8]  168.21 85.03 270 bottom
U61  NL17SZ07DFT2G_SC70-5  [SN74LVC1G07DCKR_SC70-5]  148.37 95.87 90 top
U62  NL17SZ07DFT2G_SC70-5  [SN74LVC1G07DCKR_SC70-5]  164.79 66.69 270 top
U63  NL17SZ07DFT2G_SC70-5  [SN74LVC1G07DCKR_SC70-5]  164.79 70.37 270 top
U64  NL17SZ07DFT2G_SC70-5  [SN74LVC1G07DCKR_SC70-5]  99.61 97.56 0 top
U65  NL17SZ07DFT2G_SC70-5  [SN74LVC1G07DCKR_SC70-5]  102.4 97.56 0 top
U66  NL17SZ07DFT2G_SC70-5  [SN74LVC1G07DCKR_SC70-5]  106.12 113.9 180 top
U69  -  [CY7C65211-24LTXI_QFN24_4X4]  168.84 27.14 0 bottom
U74  AP22802AW5-7 SOT25 5P  [SY6288D20AAC_SOT23-5]  190.88 150.36 180 bottom
U75  AP22802AW5-7 SOT25 5P  [SY6288D20AAC_SOT23-5]  152.74 123.71 90 top
U78  AP22802AW5-7 SOT25 5P  [SY6288D20AAC_SOT23-5]  54.08 76.51 270 top
U101  AP2138N-1.5TRG1_SOT23-3  [AP2138N-1P5TRG1_SOT23-3]  17.1 12.06 270 bottom
U2301  EM5209VF DFN 14P DUAL LOAD SW  [TPS22966DPUR_SON14_2X3]  35.29 21.22 180 top
U2407  F75303M_MSOP10  [EMC1403-2-AIZL-TR_MSOP10]  151.42 39.23 180 top
UA1  -  [ALC3234-CG_MQFN48_6X6]  180.57 10.58 90 bottom
UC1  FP4_BGA968  [FP4_BGA_968P-T]  101.27 96.72 270 bottom
UE1  KB9012QF A3 LQFP 128P_14X14  [KB9012QF-A2_LQFP128_14X14]  193.18 65.56 90 top
UE3  -  [SN74LVC1G06DCKR_SC70-5]  178.82 80.22 180 bottom
UE6  NCT3942S SOP 8P  [G993P1UF_SOP8]  90.23 140.55 0 top
UH1  MC74VHC1G08DFT2G SC70 5P  [NC7SZ08P5X_NL_SC70-5]  133.28 105.28 270 top
UI5  -  [SY6288D20AAC_SOT23-5]  18.41 34.1 90 bottom
UI7  -  [SY6288D20AAC_SOT23-5]  196.41 38.55 90 bottom
UL1  RTL8106E-CG QFN 32P E-LAN CTRL  [RTL8106EUS-CG_QFN32_4X4]  45.89 169.68 270 top
UL3  AP22802AW5-7 SOT25 5P  [SY6288C20AAC_SOT23-5]  37.96 173.93 90 top
UL4  AP22802AW5-7 SOT25 5P  [SY6288C20AAC_SOT23-5]  162.3 13.02 180 bottom
UR1  RTS5170-GR_QFN24_4X4  [RTS5179-GR_QFN24_4X4]  15.32 18.25 90 bottom
US2  SN75LVCP601RTJR_QFN20_4X4  [PS8520BTQFN20GTR2_TQFN20_4X4]  181.43 30.85 90 bottom
UV1  2160856030-A0_FCBGA631  [216-0842024-A11-MAR_FCBGA_631P]  177.29 143.96 180 bottom
UV2  -  [MC74VHC1G08DFT2G_SC70-5]  159.4 118.05 270 bottom
UV4  MC74VHC1G08DFT2G_SC70-5  [MC74VHC1G09DFT2G_SC70-5]  180.84 130.18 90 top
UV5  H5TC2G63FFR-11C FBGA 96P  [K4W1G1646E-HC12_FBGA_96P]  155.63 155.97 0 bottom
UV6  H5TC2G63FFR-11C FBGA 96P  [K4W1G1646E-HC12_FBGA_96P]  162.03 155.97 180 top
UV7  H5TC2G63FFR-11C FBGA 96P  [K4W1G1646E-HC12_FBGA_96P]  186.52 155.97 180 top
UV8  H5TC2G63FFR-11C FBGA 96P  [K4W1G1646E-HC12_FBGA_96P]  180.12 155.97 0 bottom
UV11  -  [ADM1032ARMZ_MSOP8]  181.35 131.37 90 bottom
UX3  -  [APL3512ABI-TRG_SOT23-5]  87.88 152.35 90 top
UX4  AP22802AW5-7 SOT25 5P  [SY6288C20AAC_SOT23-5]  83.58 155.96 270 bottom
UZ1  -  [RTD2168-CG_QFN32_5X5]  39.27 72.02 270 top
VDDP_SENSE  -  [TPC12]  138.11 75.82 180 bottom
Y2  48MHZ_8PF_X3S048000D81H-W  [Y_X3S048000D81H-W_4P]  110.22 106.38 180 bottom
Y3  32.768KHZ_12.5PF_CM31532768DZFT  [Y_CM31532768DZFT_2P]  131.27 105.03 0 bottom
Y9  12MHZ_18PF_7V12000001  [Y_CRG3201212_4P]  162.29 21 90 bottom
YL2  25MHZ_10PF_7V25000014  [Y_7V25000014_4P]  47.1 174.3 0 top
YV1  27MHZ_10PF_7V27000050  [Y_7V27000011_4P]  161.68 117.88 0 bottom

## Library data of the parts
C16 C24 C26 C27 C29-C34 C41 C43 C46 C62 C73 C109-C118 C124 C126 C130 C132 C134 C136-C143 C145-C148 C155 C157 C159-C161 C163 C166-C168 C174-C180 C183 C185 C186 C196 C203 C215 C223-C229 C245 C343 C349 C551 C553 C615 C635 C636 C665-C668 C682 C686 C796 C797 C912 C923 C936 C944 C945 C983 C987 C999 C1000 C1005-C1007 C1052 C1056 C1067 C1078 C1079 C1081 C1082 C1084 C1086-C1093 C1099 C1102 C1110-C1117 C1119-C1123 C1125-C1136 C1138-C1146 C1148 C1149 C1274 C1275 C1280 C2498 C2500 C2502 C2504 C2505 C4311-C4314 C4321 C4322 C5216 C5217 CA21 CA22 CA24 CA25 CA29-CA32 CA51 CA54 CA56-CA60 CA65 CA69 CD66-CD79 CE3 CE4 CE10 CE13 CE14 CE17 CE20 CE21 CE23-CE26 CE28 CE30 CE33 CE37 CE39-CE43 CE45-CE47 CE58 CH14-CH16 CH23 CI2-CI4 CI13-CI15 CI45-CI47 CL3 CL5-CL10 CL12 CL15 CL16 CL30 CL31 CL36 CL37 CL39 CL41 CM5 CM7-CM11 CR1 CR3-CR7 CR9 CR11 CS5 CS6 CS8-CS11 CS13-CS15 CS27 CS30-CS42 CV1-CV11 CV15 CV17 CV18 CV20-CV22 CV26 CV28 CV29 CV33-CV35 CV39-CV42 CV46-CV53 CV56-CV60 CV62-CV66 CV71-CV80 CV82 CV85-CV87 CV89 CV90 CV92-CV102 CV104-CV117 CV119-CV135 CV137-CV150 CV152-CV168 CV170-CV191 CV193 CV194 CV196-CV218 CV357-CV364 CVT90 CX1 CX2 CX11-CX21 CX23-CX30 CX50 CX52 CZ1 CZ2 CZ4-CZ8 CZ16-CZ23 CZ25 CZ27-CZ34 EC6104 PC1-PC8 PC13-PC16 PC102 PC103 PC108 PC111 PC113 PC114 PC201-PC203 PC207 PC208 PC210 PC214 PC301-PC303 PC309 PC401 PC402 PC404 PC501 PC507-PC509 PC512-PC516 PC518 PC520-PC523 PC601 PC603 PC606 PC705 PC708 PC711 PC742 PC744-PC749 PC751-PC753 PC758 PC759 PC765 PC768 PC769 PC777 PC779 PC803 PC805 PC1004 PC1006-PC1008 PC1010 PC1011 PC1015 PC1018 PC1037 PC1056-PC1062 PC1064 PC1066 PC1068 PC1069 PC1071 PC1072 PC1101 PC1106 PC1107 PC1115-PC1117 PC1119 PC1120 PC1122-PC1125 PC1127 PC1128 PC1130 PC1131 PC1201 PC1202 PC1204 PC1401 PC1402 PC1405 PC1408 = C_0402
C119 C120 C125 C127 C131 C133 C135 C144 C149 C150 C158 C162 C165 C431 C432 C523 C620-C623 C828 C831 C836 C934 C935 C939 C940 C949-C951 C1008-C1011 C1015 C1016 C1053-C1055 C1057-C1066 C1068-C1077 C1080 C1083 C1085 C1095-C1098 C1100 C1101 C1108 C1109 C1118 C1124 C1137 C1147 C2305 C2306 C2308 C2309 C2316 C2318 C2322-C2324 C2618-C2622 CA23 CA53 CA55 CA61-CA64 CA66-CA68 CA70 CA71 CA74 CE27 CE29 CE56 CE57 CI40 CL4 CL13 CL14 CL17 CL19 CM4 CM6 CR2 CR8 CS16 CV19 CV27 CV30 CV38 CV43-CV45 CV54 CV55 CV61 CV67-CV70 CV81 CV84 CV88 CV91 CV103 CV118 CV136 CV151 CV169 CV192 CV195 CX5 CX6 CX22 CZ3 CZ24 CZ26 PC100 PC104-PC106 PC109 PC110 PC200 PC204 PC209 PC305 PC306 PC403 PC502 PC503 PC510 PC511 PC517 PC519 PC721 PC750 PC757 PC767 PC802 PC804 PC1009 PC1012-PC1014 PC1038 PC1053-PC1055 PC1063 PC1065 PC1108-PC1111 PC1118 PC1121 PC1126 PC1129 PC1203 PC1403 PC1404 PC1413 PC1414 = C_0603
C151 C152 C156 C164 = C_D3
C2307 CE44 CI1 CI5 CI12 CI18 CI44 CS7 CS12 CX3 CX7 CX8 CX49 CX51 PC112 PC115 PC205 PC206 PC211 PC212 PC304 PC308 PC405 PC504-PC506 PC602 PC604 PC605 PC760-PC764 PC766 PC775 PC776 PC801 PC1002 PC1003 PC1039 PC1067 PC1070 PC1103-PC1105 PC1112-PC1114 PC1205 PC1406 PC1407 PC1409-PC1412 = C_0805
CI48 = C_B15G
CL33 = C_1206
CLIP1 = EMIST-SQ-26G_1P
CLIP2 CLIP4 = EMIST_SQ-55G_1P
CLRP1-CLRP5 = SHORTPADS: User Part Number: PART#
D3 = RB751V-40TE17_SOD323-2
D4 DX1 = RB751V-40_SOD323-2
D20 = PESD24VS2UT_SOT23-3
D31 D32 = DB2J31400L_SOD323-2
D101 = BAS40-04_SOT23-3
D5501 = RB551V-30_SOD323-2
DA8 = BAT54C-7-F_SOT23-3
DA13 DA14 = AZ5125-02SPR7G_SOT23-3
DI1 = IP4292CZ10-TBR_XSON10_2P5X1
DI2-DI4 = L30ESDL5V0C3-2_SOT23-3
DX2 = PESD5V0U2BT_SOT23-3
FD1-FD6 = FIDUCIAL_C40M80
FE1 = F_1812L075-24DR
FX1 = F_1206L150PR
H1 H2 H4 H5 H14 = H_3P0
H3 = H_3P0X3P8N
H6 H7 = H_3P2
H8 = H_4P0N
H21-H23 = H_3P3
H31 = H_3P4
H32 H33 = H_3P7
HDLED1 = LED_12-21C-T3D-CM2P1B18X-2C_3P
J10 J510 JP7 JP13 PJP203 PJP401 PJP402 PJP601 PJP602 PJP801 PJP802 PJP1201 PJP1202 = JUMP_43X79
J11 J509 J511 PJP100-PJP103 PJP200 PJP201 PJP301 PJP302 PJP1401 = JUMP_43X118
JCRT = C-K_80461-5K1-152_15P-T-S
JDIMM1 = FOX_AS0A621-J4SB-7H_204P
JDIMM2 = FOX_AS0A621-J4RB-7H_204P
JEDP = ACES_51540-04001-P01_40P-T
JFAN = ACES_50224-0030N-001_3P-T
JHDD1 = ACES_51625-01201-001_12P-T
JHDD2 = ACES_50208-01001-001_10P
JHDMI = C-K_96067-3K28-192-124_19P-T
JHDT1 = SAMTE_ASP-136446-07-B_20P-T
JIO1 = ACES_51524-0240N-001_24P
JKB = ACES_51510-0304N-P01_30P
JKBBL = ACES_50524-00401-P01_4P
JLAN = SANTA_130456-661_8P-T
JNGFF = DAN05-67406-0100_67P-T
JODD = ACES_51519-02001-001_20P-T
JP2 JP3 JP12 JP14 JP15 PJP1402 = JUMP_43X39
JPWR = JXT_FP202DH-004M10M_4P
JREAD = TAI_PSDATG-11GLBS1NN4H0_11P-T
JRTC = LOTES_AAA-BAT-054-K01_2P
JSPK = ACES_50224-0040N-001_4P-T
JTP = JXT_FP202DH-008M10M_8P
JUSB1 = SUYIN_020053GR009M221ZL_9P-T
L22 = KC_FBMA-L11-201209-121LMA50_2P
LA1 LV6 = MURAT_BLM15BB221SN1D_2P
LA3-LA6 LA8 LA9 PR103 PR111 PR206 PR210 PR507 PR517 PR603 PR773 PR780 PR1012 PR1026 PR1084 PR1108 PR1114 PR1126 R138 R149 R151 R152 R156 R157 R160 R1671-R1673 R1675 R5409 RE331 RL19 RL20 RL41 RL42 RV94 RX30 = R_0603
LA7 LA10 LV2-LV4 LV7 LV8 LV25 LV26 PH1 PH501 PH502 PH1000-PH1003 PH1101 PH1102 PR1-PR4 PR6-PR10 PR15 PR16 PR18 PR20 PR23 PR24 PR26-PR38 PR102 PR104-PR110 PR114 PR115 PR204 PR205 PR207 PR208 PR302 PR304 PR306-PR308 PR401-PR404 PR501-PR505 PR508 PR510-PR513 PR515 PR518-PR528 PR531-PR533 PR602 PR604 PR605 PR727 PR729 PR731 PR732 PR737-PR742 PR744-PR746 PR749-PR757 PR760 PR762-PR764 PR779 PR802 PR803 PR1000 PR1002-PR1005 PR1007 PR1009 PR1011 PR1013-PR1016 PR1018 PR1021 PR1028 PR1047 PR1051 PR1065-PR1068 PR1070-PR1073 PR1076-PR1081 PR1086 PR1087 PR1101 PR1104-PR1106 PR1110-PR1113 PR1115 PR1117 PR1119-PR1121 PR1124 PR1128-PR1137 PR1201-PR1204 PR1401-PR1403 PR1406-PR1410 R2-R10 R12-R21 R28-R31 R40-R42 R44 R49 R51-R57 R59 R73 R75 R80 R82 R90 R93 R96 R106 R107 R117 R118 R120 R122-R130 R134-R136 R139-R148 R150 R154 R155 R158 R159 R346-R348 R365 R366 R384 R400 R401 R404 R437 R438 R449 R452 R541 R542 R602 R616-R618 R634-R642 R644 R645 R654 R661-R663 R669-R672 R675-R677 R679-R683 R685 R686 R688-R696 R703-R705 R709 R808-R811 R902-R905 R907 R914 R916-R918 R925-R932 R934-R944 R949-R956 R1160 R1161 R1563 R1674 R1691-R1694 R2448 R2450 R2634-R2636 R6103-R6108 R6110 RA5 RA6 RA12 RA13 RA19 RA34 RA53 RA55 RA56 RA79-RA84 RA130 RA165 RA166 RA1109 RA1112 RA1113 RC7-RC10 RD15 RD16 RE16 RE17 RE19-RE28 RE30 RE32 RE46 RE48 RE49 RE58 RE60-RE63 RE67-RE70 RE72 RE73 RE75 RE336 RE337 RE340 RE341 RE504 RH1 RH25-RH29 RH40-RH46 RH51 RH54-RH57 RI1 RI2 RL27 RL31 RL33-RL35 RL37-RL40 RM6 RM8 RM9 RR1-RR3 RS6 RS8 RS18 RS20 RS21 RS23 RS24 RS27-RS31 RS33-RS36 RS38 RS41-RS45 RV1-RV6 RV8 RV9 RV11-RV13 RV15-RV17 RV20 RV21 RV28 RV29 RV32-RV59 RV71-RV79 RV81-RV84 RV87-RV92 RV146-RV149 RV151-RV169 RV254 RV255 RX2 RX3 RX8-RX20 RX24-RX26 RX34-RX36 RX43-RX46 RZ1-RZ6 RZ10 RZ19 RZ21 RZ42 RZ45 RZ47 RZ49 RZ51-RZ55 RZ591 RZ1045-RZ1049 = R_0402
LE3 LE4 = KC_FBMA-L11-160808-800LMT_2P
LED1 = LED_12-22A-S2ST3D-C30-2C_3P
LI1 LI3 = MURAT_DLW21SN670HQ2L_4P
LI2 LI7 LI8 LR2 LX2-LX6 = INPAQ_HCM2012GA900AE_4P
LL1 = MURAT_LQM2MPN2R2NG0L_2P
LX1 = KC_FBMA-L11-201209-221LMA30_2P
LZ1-LZ3 = CHILI_SBY100505T-470Y-N_2P
PBATT1 = SUYIN_200277GR008M270ZR_8P-T
PC101 PC107 PC213 PC307 PC310 PC836-PC839 PC953-PC956 PC959 PC960 PC967-PC969 = C_D2
PC1000 PC1001 PC1005 = C_VSS330M1ETR-0604
PD2 PD3 PD101 = TVNST52302AB0_SOT523-3
PD704-PD706 = SDMK0340L-7-F_SOD323-2
PJP1-PJP3 PJP204 PJP303 PJP501 PJP1001 PJP1101 PJP1403 = JUMP_43X79-NPM
PJP104 PJP701 = JUMP_43X118-NPM
PJPDC1 = ACES_50458-00601-001_6P-T
PL1 PL3 PL4 PL102 PL201 PL301 PL501 PL1001 PL1101 PL1401 = MURAT_BLM41PG600SN1L_2P
PL2 = MURAT_BLM15AG102SN1D_2P
PL100 PL101 PL200 PL700 = L_7X7X3_M_2P
PL302 = CYNTE_PCMB104T-1R0MH_2P
PL502 PL1002 PL1004 PL1102 PL1103 = TOKO_FDUM0640J-H-R36M-P3_4P
PL601 = TAIYO_NRS4018T1R0NDGJ_2P
PL704 = L_5X5X3_M_2P
PL1402 = CYNTE_PCMB053T-1R0MS_2P
PQ1-PQ4 PQ707 PQ709 = 2N7002DW-T-R7_SOT363-6
PQ5 = RHU002N06_SOT323-3
PQ6 = FDV301N_NL_SOT23-3
PQ101-PQ104 PQ200 PQ201 PQ704 PQ708 PQ740 = SIS412DN-T1-GE3_POWERPAK8-5
PQ301 PQ302 PQ501-PQ503 PQ717 PQ718 PQ1007-PQ1009 PQ1101-PQ1106 = SIR472DP-T1-GE3_POWERPAK8-5
PQ504 PQ801 QH1 QM1 = SSM3K7002FU_SC70-3
PQ710 = DTA144EUA_SC70-3
PQ711 = DTC115EUA_SC70-3
PQ1001 = AON6970_DFN5X6D-8-7
PR5 PR112 PR113 PR203 PR305 PR516 PR721 PR722 PR743 PR766 PR1010 PR1074 PR1107 PR1125 PR1404 RM7 RM10 = R_1206
PR100 PR101 PR201 PR202 PR301 PR506 PR509 PR529 PR530 PR601 PR769 PR770 PR772 PR774-PR778 PR801 PR1006 PR1023 PR1069 PR1075 PR1085 PR1116 PR1122 PR1138 PR1139 R11 R22-R27 R119 R153 R407 R450 R664 R673 R1690 R2313 R2318 RA8 RA10 RD19 RE14 RE15 RE31 RE33 RE35 RE39 RE42 RE53-RE56 RE64-RE66 RE71 RE80 RE338 RH30-RH32 RH52 RH53 RS19 RS22 RS25 RS26 RS37 RX7 RX23 = R0402_0OHM
PR200 PR303 PR514 PR761 PR771 PR781 PR1008 PR1082 PR1103 PR1123 PR1405 RA29-RA32 RA1110 RA1111 RE330 RL6 RV27 RV30 RV60 RV93 RX27-RX29 = R0603_0OHM
PR703 PR765 = R_1206_4P
PU100 = TPS51285BRUKR_QFN20_3X3
PU200 = RT8207MZQW_WQFN20_3X3
PU300 = TPS51212DSCR_SON10_3X3
PU400 PU1200 = APL5930KAI-TRG_SO8
PU500 PU1001 PU1100 = ISL62771HRTZ-T_TQFN40_5X5
PU600 = SY8003DFC_DFN8_2X2
PU703 = ISL95812HRZ-T_QFN32_4X4
PU800 = APL5336KAI-TRL_SOP8P8
PU1400 = SYX198DQNC_QFN10_3X3
Q20 Q83 Q84 Q87 Q89 Q91-Q93 Q6101 Q6102 Q6104 QX3 = 2N7002K_SOT23-3
Q52 Q79 Q2505 Q2507 Q2509 Q2516 QA6 QV8 QX4 = DMN66D0LDW-7_SOT363-6
Q135 Q2513-Q2515 = AO3416_SOT23-3
Q2407 Q2408 = MMST3904-7-F_SOT323-3
Q6103 Q6105 QS3 = 2N7002KW_SOT323-3
QC1 = MESS138W-G_SOT323-3
QE4 = 2N7002BKW_SOT323-3
QE5 QS2 = SI3456BDV-T1-E3_TSOP6
QV1 = 2N7002KDWH_SOT363-6
QX5 = MMBT3904_NL_SOT23-3
RE4 RE13 RE59 RX4 = R_0805
RL1 = MURAT_BLM18AG601SN1D_L0603_2P
RP13 RP20 RP24 RP25 RP27 RP28 RP30 RP34 RP45 RP58 RP59 RP62 RP63 RPE1 = RP_0804_8P4R
RV31 = R0805_0OHM
RX21 RX22 RX31 RX32 RX37-RX42 = R_0402-NPM
SW1 = SW_SMT1-05-A_4P
T12 T13 T26-T36 T38-T46 T86 T94 T95 T173 T201-T218 T221-T224 T4933-T4935 VDDP_SENSE = TPC12
TL1 TL2 = LANKO_LF-H1201P-2_16P
U1 = SN74LVC2T45DCTR_SM8
U2 = LM393DR_SO8
U4 = AO4430L_SO8
U5 UV2 = MC74VHC1G08DFT2G_SC70-5
U15 U2301 = TPS22966DPUR_SON14_2X3
U56 = W25Q64DWSSIG_SO8
U61-U66 = SN74LVC1G07DCKR_SC70-5
U69 = CY7C65211-24LTXI_QFN24_4X4
U74 U75 U78 UI5 UI7 = SY6288D20AAC_SOT23-5
U101 = AP2138N-1P5TRG1_SOT23-3
U2407 = EMC1403-2-AIZL-TR_MSOP10
UA1 = ALC3234-CG_MQFN48_6X6
UC1 = FP4_BGA_968P-T
UE1 = KB9012QF-A2_LQFP128_14X14
UE3 = SN74LVC1G06DCKR_SC70-5
UE6 = G993P1UF_SOP8
UH1 = NC7SZ08P5X_NL_SC70-5
UL1 = RTL8106EUS-CG_QFN32_4X4
UL3 UL4 UX4 = SY6288C20AAC_SOT23-5
UR1 = RTS5179-GR_QFN24_4X4
US2 = PS8520BTQFN20GTR2_TQFN20_4X4
UV1 = 216-0842024-A11-MAR_FCBGA_631P
UV4 = MC74VHC1G09DFT2G_SC70-5
UV5-UV8 = K4W1G1646E-HC12_FBGA_96P
UV11 = ADM1032ARMZ_MSOP8
UX3 = APL3512ABI-TRG_SOT23-5
UZ1 = RTD2168-CG_QFN32_5X5
Y2 = Y_X3S048000D81H-W_4P
Y3 = Y_CM31532768DZFT_2P
Y9 = Y_CRG3201212_4P
YL2 = Y_7V25000014_4P
YV1 = Y_7V27000011_4P

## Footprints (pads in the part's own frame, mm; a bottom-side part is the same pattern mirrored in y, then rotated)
2N7002BKW_SOT323-3
  oval 0.61x0.559 smd: 1(0,0) 2(-0.65,-1.85) 3(0.65,-1.85)
2N7002DW-T-R7_SOT363-6
  oval 0.381x1.397 smd: 1(0,0) 2(0.65,0) 3(1.3,0) 4(1.3,1.725) 5(0.65,1.725) 6(0,1.725)
2N7002K_SOT23-3
  oval 1.016x1.524 smd: 1(0,0) 2(0.965,2.083) 3(-0.965,2.083)
2N7002KDWH_SOT363-6
  oval 0.356x0.889 smd: 1(0,0) 2(0.65,0) 3(1.3,0) 4(1.3,1.6) 5(0.65,1.6) 6(0,1.6)
2N7002KW_SOT323-3
  oval 0.813x0.914 smd: 1(0,0) 2(0.65,1.6) 3(-0.65,1.6)
216-0842024-A11-MAR_FCBGA_631P
  round 0.406 smd: A3(0.8,0) A30(20.8,0) A32(21.6,0) AB7(3.2,-15) AB8(4,-15) AB9(4.8,-15) AB10(5.6,-15) AB23(16,-15) AB24(16.8,-15) AB25(17.6,-15) AB26(18.4,-15) AC11(6.6,-16) AC13(7.8,-16) AC14(9,-16) AC16(10.2,-16) AC17(11.4,-16) AC19(12.6,-16) AC20(13.8,-16) AC22(15,-16) AD11(6.6,-16.8) AD13(7.8,-16.8) AD14(9,-16.8) AD16(10.2,-16.8) AD17(11.4,-16.8) AD19(12.6,-16.8) AD20(13.8,-16.8) AD22(15,-16.8) AE11(6.6,-17.6) AE13(7.8,-17.6) AE14(9,-17.6) AE16(10.2,-17.6) AE17(11.4,-17.6) AE19(12.6,-17.6) AE20(13.8,-17.6) AE22(15,-17.6) AF11(6.6,-18.4) AF13(7.8,-18.4) AF14(9,-18.4) AF16(10.2,-18.4) AF17(11.4,-18.4) AF19(12.6,-18.4) AF20(13.8,-18.4) AF22(15,-18.4) AK1(0,-20.8) AK3(0.8,-20.8) AK30(20.8,-20.8) AK32(21.6,-20.8) AM1(0,-21.6) AM3(0.8,-21.6) AM30(20.8,-21.6) AM32(21.6,-21.6) C1(0,-0.8) C3(0.8,-0.8) C30(20.8,-0.8) C32(21.6,-0.8) G11(6.6,-3.2) G13(7.8,-3.2) G14(9,-3.2) G16(10.2,-3.2) G17(11.4,-3.2) G19(12.6,-3.2) G20(13.8,-3.2) G22(15,-3.2) H11(6.6,-4) H13(7.8,-4) H14(9,-4) H16(10.2,-4) H17(11.4,-4) H19(12.6,-4) H20(13.8,-4) H22(15,-4) J11(6.6,-4.8) J13(7.8,-4.8) J14(9,-4.8) J16(10.2,-4.8) J17(11.4,-4.8) J19(12.6,-4.8) J20(13.8,-4.8) J22(15,-4.8) K11(6.6,-5.6) K13(7.8,-5.6) K14(9,-5.6) K16(10.2,-5.6) K17(11.4,-5.6) K19(12.6,-5.6) K20(13.8,-5.6) K22(15,-5.6) L7(3.2,-6.6) L8(4,-6.6) L9(4.8,-6.6) L10(5.6,-6.6) L23(16,-6.6) L24(16.8,-6.6) L25(17.6,-6.6) L26(18.4,-6.6) N7(3.2,-7.8) N8(4,-7.8) N9(4.8,-7.8) N10(5.6,-7.8) N23(16,-7.8) N24(16.8,-7.8) N25(17.6,-7.8) N26(18.4,-7.8) P7(3.2,-9) P8(4,-9) P9(4.8,-9) P10(5.6,-9) P23(16,-9) P24(16.8,-9) P25(17.6,-9) P26(18.4,-9) T7(3.2,-10.2) T8(4,-10.2) T9(4.8,-10.2) T10(5.6,-10.2) T23(16,-10.2) T24(16.8,-10.2) T25(17.6,-10.2) T26(18.4,-10.2) U7(3.2,-11.4) U8(4,-11.4) U9(4.8,-11.4) U10(5.6,-11.4) U23(16,-11.4) U24(16.8,-11.4) U25(17.6,-11.4) U26(18.4,-11.4) W7(3.2,-12.6) W8(4,-12.6) W9(4.8,-12.6) W10(5.6,-12.6) W23(16,-12.6) W24(16.8,-12.6) W25(17.6,-12.6) W26(18.4,-12.6) Y7(3.2,-13.8) Y8(4,-13.8) Y9(4.8,-13.8) Y10(5.6,-13.8) Y23(16,-13.8) Y24(16.8,-13.8) Y25(17.6,-13.8) Y26(18.4,-13.8)
  round 0.305 smd: A5(1.6,0) A7(3.2,0) A9(4.8,0) A11(6.4,0) A13(8,0) A15(9.6,0) A17(11.2,0) A19(12.8,0) A21(14.4,0) A23(16,0) A25(17.6,0) A27(19.2,0) A28(20,0) AA1(0,-14.4) AA3(0.8,-14.4) AA5(1.6,-14.4) AA6(2.4,-14.4) AA27(19.2,-14.4) AA29(20.4,-14.4) AA31(21.2,-14.4) AB2(0.4,-15.2) AB4(1.2,-15.2) AB6(2.4,-15.2) AB27(19.2,-15.2) AB28(20,-15.2) AB30(20.8,-15.2) AB32(21.6,-15.2) AC1(0,-16) AC3(0.8,-16) AC5(1.6,-16) AC6(2.4,-16) AC7(3.2,-16) AC8(4,-16) AC9(4.8,-16) AC10(5.6,-16) AC23(16,-16) AC24(16.8,-16) AC25(17.6,-16) AC26(18.4,-16) AC27(19.2,-16) AC29(20.4,-16) AC31(21.2,-16) AD2(0.4,-16.8) AD4(1.2,-16.8) AD6(2.4,-16.8) AD7(3.2,-16.8) AD8(4,-16.8) AD9(4.8,-16.8) AD10(5.6,-16.8) AD23(16,-16.8) AD24(16.8,-16.8) AD25(17.6,-16.8) AD26(18.4,-16.8) AD27(19.2,-16.8) AD28(20,-16.8) AD30(20.8,-16.8) AD32(21.6,-16.8) AE1(0,-17.6) AE3(0.8,-17.6) AE5(1.6,-17.6) AE6(2.4,-17.6) AE7(3.2,-17.6) AE8(4,-17.6) AE9(4.8,-17.6) AE10(5.6,-17.6) AE23(16,-17.6) AE24(16.8,-17.6) AE25(17.6,-17.6) AE26(18.4,-17.6) AE27(19.2,-17.6) AE29(20.4,-17.6) AE31(21.2,-17.6) AF2(0.4,-18.4) AF4(1.2,-18.4) AF6(2.4,-18.4) AF7(3.2,-18.4) AF8(4,-18.4) AF9(4.8,-18.4) AF10(5.6,-18.4) AF23(16,-18.4) AF24(16.8,-18.4) AF25(17.6,-18.4) AF26(18.4,-18.4) AF27(19.2,-18.4) AF28(20,-18.4) AF30(20.8,-18.4) AF32(21.6,-18.4) AG1(0,-19.2) AG3(0.8,-19.2) AG5(1.6,-19.2) AG6(2.4,-19.2) AG7(3.2,-19.2) AG8(4,-19.2) AG9(4.8,-19.2) AG10(5.6,-19.2) AG11(6.4,-19.2) AG12(7.2,-19.2) AG13(8,-19.2) AG14(8.8,-19.2) AG15(9.6,-19.2) AG16(10.4,-19.2) AG17(11.2,-19.2) AG18(12,-19.2) AG19(12.8,-19.2) AG20(13.6,-19.2) AG21(14.4,-19.2) AG22(15.2,-19.2) AG23(16,-19.2) AG24(16.8,-19.2) AG25(17.6,-19.2) AG26(18.4,-19.2) AG27(19.2,-19.2) AG29(20.4,-19.2) AG31(21.2,-19.2) AH1(0,-20) AH3(0.8,-20) AH5(1.6,-20) AH6(2.4,-20) AH8(4,-20) AH10(5.6,-20) AH12(7.2,-20) AH14(8.8,-20) AH16(10.4,-20) AH18(12,-20) AH20(13.6,-20) AH22(15.2,-20) AH24(16.8,-20) AH26(18.4,-20) AH28(20,-20) AH30(20.8,-20) AH32(21.6,-20) AJ7(3.2,-20.4) AJ9(4.8,-20.4) AJ11(6.4,-20.4) AJ13(8,-20.4) AJ15(9.6,-20.4) AJ17(11.2,-20.4) AJ19(12.8,-20.4) AJ21(14.4,-20.4) AJ23(16,-20.4) AJ25(17.6,-20.4) AJ27(19.2,-20.4) AK5(1.6,-20.8) AK6(2.4,-20.8) AK8(4,-20.8) AK10(5.6,-20.8) AK12(7.2,-20.8) AK14(8.8,-20.8) AK16(10.4,-20.8) AK18(12,-20.8) AK20(13.6,-20.8) AK22(15.2,-20.8) AK24(16.8,-20.8) AK26(18.4,-20.8) AK28(20,-20.8) AL7(3.2,-21.2) AL9(4.8,-21.2) AL11(6.4,-21.2) AL13(8,-21.2) AL15(9.6,-21.2) AL17(11.2,-21.2) AL19(12.8,-21.2) AL21(14.4,-21.2) AL23(16,-21.2) AL25(17.6,-21.2) AL27(19.2,-21.2) AM5(1.6,-21.6) AM6(2.4,-21.6) AM8(4,-21.6) AM10(5.6,-21.6) AM12(7.2,-21.6) AM14(8.8,-21.6) AM16(10.4,-21.6) AM18(12,-21.6) AM20(13.6,-21.6) AM22(15.2,-21.6) AM24(16.8,-21.6) AM26(18.4,-21.6) AM28(20,-21.6) B6(2.4,-0.4) B8(4,-0.4) B10(5.6,-0.4) B12(7.2,-0.4) B14(8.8,-0.4) B16(10.4,-0.4) B18(12,-0.4) B20(13.6,-0.4) B22(15.2,-0.4) B24(16.8,-0.4) B26(18.4,-0.4) C5(1.6,-0.8) C7(3.2,-0.8) C9(4.8,-0.8) C11(6.4,-0.8) C13(8,-0.8) C15(9.6,-0.8) C17(11.2,-0.8) C19(12.8,-0.8) C21(14.4,-0.8) C23(16,-0.8) C25(17.6,-0.8) C27(19.2,-0.8) C28(20,-0.8) D6(2.4,-1.2) D8(4,-1.2) D10(5.6,-1.2) D12(7.2,-1.2) D14(8.8,-1.2) D16(10.4,-1.2) D18(12,-1.2) D20(13.6,-1.2) D22(15.2,-1.2) D24(16.8,-1.2) D26(18.4,-1.2) E1(0,-1.6) E3(0.8,-1.6) E5(1.6,-1.6) E7(3.2,-1.6) E9(4.8,-1.6) E11(6.4,-1.6) E13(8,-1.6) E15(9.6,-1.6) E17(11.2,-1.6) E19(12.8,-1.6) E21(14.4,-1.6) E23(16,-1.6) E25(17.6,-1.6) E27(19.2,-1.6) E28(20,-1.6) E30(20.8,-1.6) E32(21.6,-1.6) F2(0.4,-2.4) F4(1.2,-2.4) F6(2.4,-2.4) F7(3.2,-2.4) F8(4,-2.4) F9(4.8,-2.4) F10(5.6,-2.4) F11(6.4,-2.4) F12(7.2,-2.4) F13(8,-2.4) F14(8.8,-2.4) F15(9.6,-2.4) F16(10.4,-2.4) F17(11.2,-2.4) F18(12,-2.4) F19(12.8,-2.4) F20(13.6,-2.4) F21(14.4,-2.4) F22(15.2,-2.4) F23(16,-2.4) F24(16.8,-2.4) F25(17.6,-2.4) F26(18.4,-2.4) F27(19.2,-2.4) F28(20,-2.4) F30(20.8,-2.4) F32(21.6,-2.4) G1(0,-3.2) G3(0.8,-3.2) G5(1.6,-3.2) G6(2.4,-3.2) G7(3.2,-3.2) G8(4,-3.2) G9(4.8,-3.2) G10(5.6,-3.2) G23(16,-3.2) G24(16.8,-3.2) G25(17.6,-3.2) G26(18.4,-3.2) G27(19.2,-3.2) G29(20.4,-3.2) G31(21.2,-3.2) H2(0.4,-4) H4(1.2,-4) H6(2.4,-4) H7(3.2,-4) H8(4,-4) H9(4.8,-4) H10(5.6,-4) H23(16,-4) H24(16.8,-4) H25(17.6,-4) H26(18.4,-4) H27(19.2,-4) H28(20,-4) H30(20.8,-4) H32(21.6,-4) J1(0,-4.8) J3(0.8,-4.8) J5(1.6,-4.8) J6(2.4,-4.8) J7(3.2,-4.8) J8(4,-4.8) J9(4.8,-4.8) J10(5.6,-4.8) J23(16,-4.8) J24(16.8,-4.8) J25(17.6,-4.8) J26(18.4,-4.8) J27(19.2,-4.8) J29(20.4,-4.8) J31(21.2,-4.8) K2(0.4,-5.6) K4(1.2,-5.6) K6(2.4,-5.6) K7(3.2,-5.6) K8(4,-5.6) K9(4.8,-5.6) K10(5.6,-5.6) K23(16,-5.6) K24(16.8,-5.6) K25(17.6,-5.6) K26(18.4,-5.6) K27(19.2,-5.6) K28(20,-5.6) K30(20.8,-5.6) K32(21.6,-5.6) L1(0,-6.4) L3(0.8,-6.4) L5(1.6,-6.4) L6(2.4,-6.4) L27(19.2,-6.4) L29(20.4,-6.4) L31(21.2,-6.4) M2(0.4,-7.2) M4(1.2,-7.2) M6(2.4,-7.2) M27(19.2,-7.2) M28(20,-7.2) M30(20.8,-7.2) M32(21.6,-7.2) N1(0,-8) N3(0.8,-8) N5(1.6,-8) N6(2.4,-8) N27(19.2,-8) N29(20.4,-8) N31(21.2,-8) P2(0.4,-8.8) P4(1.2,-8.8) P6(2.4,-8.8) P27(19.2,-8.8) P28(20,-8.8) P30(20.8,-8.8) P32(21.6,-8.8) R1(0,-9.6) R3(0.8,-9.6) R5(1.6,-9.6) R6(2.4,-9.6) R27(19.2,-9.6) R29(20.4,-9.6) R31(21.2,-9.6) T2(0.4,-10.4) T4(1.2,-10.4) T6(2.4,-10.4) T27(19.2,-10.4) T28(20,-10.4) T30(20.8,-10.4) T32(21.6,-10.4) U1(0,-11.2) U3(0.8,-11.2) U5(1.6,-11.2) U6(2.4,-11.2) U27(19.2,-11.2) U29(20.4,-11.2) U31(21.2,-11.2) V2(0.4,-12) V4(1.2,-12) V6(2.4,-12) V27(19.2,-12) V28(20,-12) V30(20.8,-12) V32(21.6,-12) W1(0,-12.8) W3(0.8,-12.8) W5(1.6,-12.8) W6(2.4,-12.8) W27(19.2,-12.8) W29(20.4,-12.8) W31(21.2,-12.8) Y2(0.4,-13.6) Y4(1.2,-13.6) Y6(2.4,-13.6) Y27(19.2,-13.6) Y28(20,-13.6) Y30(20.8,-13.6) Y32(21.6,-13.6)
  round 0.508 smd: AA11(6.4,-14.2) AA12(7.4,-14.2) AA13(8.4,-14.2) AA15(9.4,-14.2) AA16(10.4,-14.2) AA17(11.2,-14.2) AA18(12.2,-14.2) AA20(13.2,-14.2) AA21(14.2,-14.2) AA22(15.2,-14.2) AB11(6.4,-15.2) AB12(7.4,-15.2) AB13(8.4,-15.2) AB15(9.4,-15.2) AB16(10.4,-15.2) AB17(11.2,-15.2) AB18(12.2,-15.2) AB20(13.2,-15.2) AB21(14.2,-15.2) AB22(15.2,-15.2) L11(6.4,-6.4) L12(7.4,-6.4) L13(8.4,-6.4) L15(9.4,-6.4) L16(10.4,-6.4) L17(11.2,-6.4) L18(12.2,-6.4) L20(13.2,-6.4) L21(14.2,-6.4) L22(15.2,-6.4) M11(6.4,-7.4) M12(7.4,-7.4) M13(8.4,-7.4) M15(9.4,-7.4) M16(10.4,-7.4) M17(11.2,-7.4) M18(12.2,-7.4) M20(13.2,-7.4) M21(14.2,-7.4) M22(15.2,-7.4) N11(6.4,-8.4) N12(7.4,-8.4) N13(8.4,-8.4) N15(9.4,-8.4) N16(10.4,-8.4) N17(11.2,-8.4) N18(12.2,-8.4) N20(13.2,-8.4) N21(14.2,-8.4) N22(15.2,-8.4) R11(6.4,-9.4) R12(7.4,-9.4) R13(8.4,-9.4) R15(9.4,-9.4) R16(10.4,-9.4) R17(11.2,-9.4) R18(12.2,-9.4) R20(13.2,-9.4) R21(14.2,-9.4) R22(15.2,-9.4) T11(6.4,-10.4) T12(7.4,-10.4) T13(8.4,-10.4) T15(9.4,-10.4) T16(10.4,-10.4) T17(11.2,-10.4) T18(12.2,-10.4) T20(13.2,-10.4) T21(14.2,-10.4) T22(15.2,-10.4) U11(6.4,-11.2) U12(7.4,-11.2) U13(8.4,-11.2) U15(9.4,-11.2) U16(10.4,-11.2) U17(11.2,-11.2) U18(12.2,-11.2) U20(13.2,-11.2) U21(14.2,-11.2) U22(15.2,-11.2) V11(6.4,-12.2) V12(7.4,-12.2) V13(8.4,-12.2) V15(9.4,-12.2) V16(10.4,-12.2) V17(11.2,-12.2) V18(12.2,-12.2) V20(13.2,-12.2) V21(14.2,-12.2) V22(15.2,-12.2) Y11(6.4,-13.2) Y12(7.4,-13.2) Y13(8.4,-13.2) Y15(9.4,-13.2) Y16(10.4,-13.2) Y17(11.2,-13.2) Y18(12.2,-13.2) Y20(13.2,-13.2) Y21(14.2,-13.2) Y22(15.2,-13.2)
